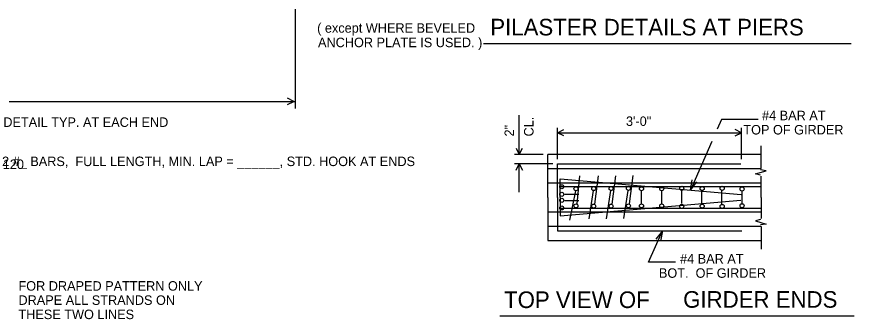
# Model space of a CAD drawing. Extents: x 1005 to 1123, y 2008 to 2074.
# Drawn here: x 1047.9 to 1077.32, y 2040.42 to 2051.04 of the extents above; entities that cross this region are included whole.
import ezdxf

# ---------------------------------------------------------------- set-up
doc = ezdxf.new("R2010")
doc.units = 0
for name, color, linetype in [('Level 2', 7, 'Continuous'), ('Level 6', 7, 'Continuous'), ('Level 60', 7, 'Continuous'), ('Level 7', 7, 'Continuous')]:
    doc.layers.add(name, color=color, linetype=linetype)

msp = doc.modelspace()

# ---------------------------------------------------------------- linework, layer by layer
at = {"layer": 'Level 2'}
for p, q in [((1057.695, 2047.823), (1057.695, 2052.087)), ((1018.361, 2048.066), (1057.695, 2048.066)), ((1065.555, 2046.209), (1065.555, 2047.587)), ((1072.658, 2047.432), (1072.511, 2047.097)), ((1073.942, 2047.432), (1072.658, 2047.432)), ((1066.896, 2046.043), (1066.896, 2047.136)), ((1073.357, 2046.043), (1073.357, 2047.136)), ((1066.896, 2046.969), (1073.357, 2046.969)), ((1066.902, 2046.55), (1066.902, 2046.823)), ((1072.32, 2046.663), (1071.568, 2044.953)), ((1074.046, 2045.717), (1074.046, 2046.514)), ((1066.396, 2046.209), (1065.389, 2046.209)), ((1066.562, 2044.699), (1066.562, 2046.209)), ((1074.046, 2046.209), (1066.562, 2046.209)), ((1066.729, 2045.876), (1065.389, 2045.876)), ((1065.555, 2044.876), (1065.555, 2045.876)), ((1066.562, 2045.709), (1074.046, 2045.709)), ((1066.896, 2045.876), (1073.332, 2045.876)), ((1066.896, 2044.699), (1066.896, 2045.876)), ((1073.851, 2045.522), (1074.225, 2045.636)), ((1074.225, 2045.636), (1074.03, 2045.669)), ((1066.993, 2045.344), (1073.349, 2044.801)), ((1066.993, 2044.699), (1066.993, 2045.344)), ((1067.583, 2044.473), (1067.679, 2045.459)), ((1068.204, 2044.462), (1068.333, 2045.459)), ((1068.814, 2044.462), (1068.943, 2045.459)), ((1069.425, 2044.47), (1069.554, 2045.467)), ((1071.568, 2044.953), (1071.631, 2045.319)), ((1074.03, 2045.474), (1073.851, 2045.522)), ((1074.046, 2044.699), (1074.046, 2045.441)), ((1066.562, 2045.209), (1074.046, 2045.209)), ((1067.001, 2045.083), (1068.171, 2045.083)), ((1068.188, 2045.083), (1074.046, 2045.083)), ((1071.568, 2044.953), (1071.796, 2045.246)), ((1067.156, 2044.815), (1067.643, 2044.815)), ((1067.336, 2043.894), (1067.54, 2044.923)), ((1068.011, 2043.948), (1068.161, 2044.934)), ((1068.622, 2043.948), (1068.772, 2044.934)), ((1069.232, 2043.956), (1069.382, 2044.941)), ((1069.846, 2044.475), (1069.846, 2044.929)), ((1070.558, 2044.475), (1070.558, 2044.929)), ((1071.26, 2044.487), (1071.26, 2044.945)), ((1071.972, 2044.463), (1071.972, 2044.947)), ((1072.674, 2044.451), (1072.674, 2044.934)), ((1073.378, 2044.475), (1073.378, 2044.921)), ((1066.562, 2044.699), (1066.562, 2043.189)), ((1066.896, 2044.699), (1066.896, 2043.523)), ((1066.993, 2044.699), (1066.993, 2044.055)), ((1066.993, 2044.055), (1073.333, 2044.596)), ((1067.156, 2044.583), (1067.643, 2044.583)), ((1074.046, 2044.699), (1074.046, 2043.958)), ((1066.562, 2044.189), (1074.046, 2044.189)), ((1067.001, 2044.315), (1068.171, 2044.315)), ((1068.188, 2044.315), (1074.046, 2044.315)), ((1074.03, 2043.925), (1073.851, 2043.876)), ((1073.851, 2043.876), (1074.225, 2043.763)), ((1066.562, 2043.689), (1074.046, 2043.689)), ((1074.225, 2043.763), (1074.03, 2043.73)), ((1074.046, 2043.681), (1074.046, 2042.885)), ((1066.896, 2043.523), (1073.366, 2043.523)), ((1070.094, 2042.418), (1070.58, 2043.523)), ((1070.58, 2043.523), (1070.352, 2043.229)), ((1070.58, 2043.523), (1070.517, 2043.157)), ((1066.562, 2043.189), (1074.046, 2043.189)), ((1071.046, 2042.418), (1070.094, 2042.418)), ((1064.869, 2040.542), (1077.32, 2040.542))]:
    msp.add_line(p, q, dxfattribs=at)
for points in [[(1057.408, 2047.959), (1057.631, 2048.07), (1057.408, 2048.181)], [(1067.118, 2046.858), (1066.896, 2046.969), (1067.118, 2047.081)], [(1073.134, 2046.858), (1073.357, 2046.969), (1073.134, 2047.081)], [(1065.444, 2046.432), (1065.555, 2046.209), (1065.666, 2046.432)], [(1065.444, 2045.654), (1065.555, 2045.876), (1065.666, 2045.654)]]:
    msp.add_lwpolyline(points, dxfattribs=at)
for centre in [(1067.048, 2045.073), (1067.544, 2045), (1068.17, 2045.008), (1068.78, 2045.008), (1069.39, 2045.016), (1069.847, 2045), (1070.559, 2045), (1071.262, 2045.016), (1071.978, 2045.008), (1072.681, 2045.016), (1073.38, 2044.992), (1067.048, 2044.805), (1067.048, 2044.594), (1067.544, 2044.399), (1068.17, 2044.391), (1068.78, 2044.391), (1069.39, 2044.399), (1069.847, 2044.399), (1070.559, 2044.399), (1071.262, 2044.383), (1071.978, 2044.391), (1072.681, 2044.383), (1073.38, 2044.406), (1067.048, 2044.326)]:
    msp.add_circle(centre, 0.0708, dxfattribs=at)
at = {"layer": 'Level 7'}
msp.add_line((1064.295, 2050.106), (1077.206, 2050.106), dxfattribs=at)

# ---------------------------------------------------------------- texts
at = {"layer": 'Level 2'}
for s, height, p in [('#4 BAR AT', 0.3333, (1074.082, 2047.407)), ('DETAIL TYP. AT EACH END', 0.33333, (1047.432, 2047.173)), ('3\'-0"', 0.3333, (1069.303, 2047.207)), ('   TOP OF GIRDER', 0.33333, (1073.054, 2046.907)), ('2 #_ BARS,  FULL LENGTH, MIN. LAP = ______, STD. HOOK AT ENDS', 0.33333, (1047.389, 2045.797)), ('#4 BAR AT', 0.3333, (1071.202, 2042.374)), ('   BOT.  OF GIRDER', 0.33333, (1070.088, 2041.874)), ('FOR DRAPED PATTERN ONLY', 0.33333, (1047.964, 2041.423)), ('DRAPE ALL STRANDS ON', 0.33333, (1047.964, 2040.923)), ('TOP VIEW OF', 0.58333, (1065.021, 2040.812)), (' GIRDER ENDS', 0.58333, (1071.094, 2040.823)), ('THESE TWO LINES', 0.33333, (1047.964, 2040.423))]:
    msp.add_text(s, height=height, dxfattribs=at).set_placement(p)
for s, p in [('CL.', (1066.055, 2046.837)), ('2"', (1065.37, 2046.837))]:
    msp.add_text(s, height=0.3333, rotation=90, dxfattribs=at).set_placement(p)
at = {"layer": 'Level 6'}
for s, p in [('( except WHERE BEVELED', (1058.455, 2050.481)), ('ANCHOR PLATE IS USED. )', (1058.486, 2049.973))]:
    msp.add_text(s, height=0.33333, dxfattribs=at).set_placement(p)
at = {"layer": 'Level 60'}
msp.add_text('120', height=0.3333, dxfattribs=at).set_placement((1047.413, 2045.694))
at = {"layer": 'Level 7'}
msp.add_text('PILASTER DETAILS AT PIERS', height=0.58333, dxfattribs=at).set_placement((1064.536, 2050.385))

doc.saveas('drawing.dxf')
